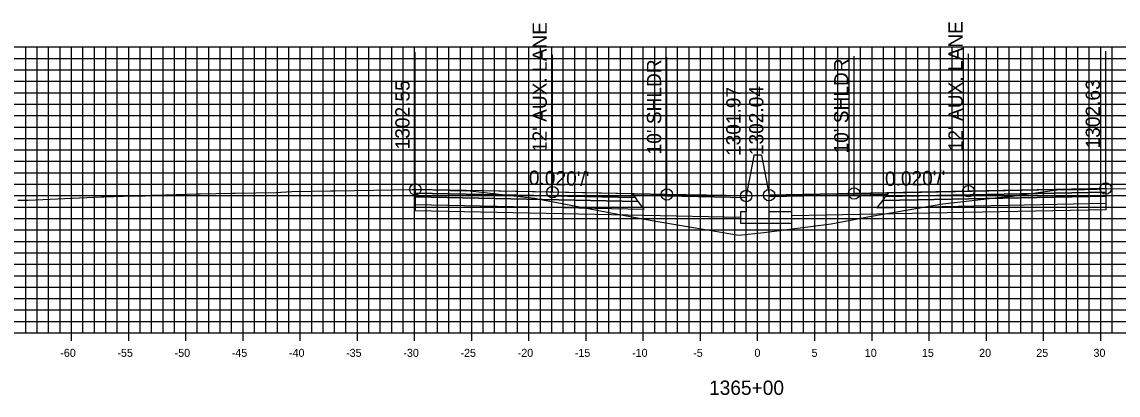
# Model space of a CAD drawing. Extents: x 674939 to 678919, y 750652 to 765176.
# Drawn here: x 678674.2 to 678770, y 754257.1 to 754289.7 of the extents above; entities that cross this region are included whole.
import ezdxf

# ---------------------------------------------------------------- set-up
doc = ezdxf.new("R2010")
doc.units = 0
for name, color, linetype in [('Level 10', 7, 'Continuous'), ('Level 17', 7, 'Continuous'), ('Level 18', 7, 'Continuous'), ('Level 19', 7, 'Continuous'), ('Level 20', 7, 'Continuous'), ('Level 22', 7, 'Continuous'), ('Level 23', 7, 'Continuous'), ('Level 4', 7, 'Continuous'), ('Level 8', 7, 'Continuous'), ('Level 9', 7, 'Continuous')]:
    doc.layers.add(name, color=color, linetype=linetype)

msp = doc.modelspace()

# ---------------------------------------------------------------- linework, layer by layer
at = {"layer": 'Level 10'}
msp.add_lwpolyline([(678673.826, 754274.146), (678674.4, 754274.144), (678674.446, 754274.145), (678674.752, 754274.161), (678681.152, 754274.436), (678681.365, 754274.444), (678683.059, 754274.507), (678684.564, 754274.521), (678684.623, 754274.523), (678684.656, 754274.525), (678684.987, 754274.544), (678685.002, 754274.546), (678685.611, 754274.58), (678685.824, 754274.586), (678689.588, 754274.707), (678689.789, 754274.712), (678692.612, 754274.752), (678692.848, 754274.757), (678696.424, 754274.838), (678696.448, 754274.837), (678696.823, 754274.85), (678696.859, 754274.855), (678697.8, 754274.9), (678701.187, 754274.964), (678701.519, 754274.97), (678701.59, 754274.972), (678708.326, 754275.093), (678708.596, 754275.097), (678708.599, 754275.097), (678708.635, 754275.098), (678710.141, 754275.048), (678710.236, 754275.044), (678710.247, 754275.046), (678711, 754275.056), (678711.565, 754275.019), (678711.707, 754275.012), (678713.024, 754274.978), (678713.042, 754274.98), (678713.133, 754274.991), (678716.186, 754274.644), (678718.748, 754274.354), (678719.049, 754274.317), (678719.41, 754274.249), (678720.813, 754273.978), (678727.53, 754272.685), (678729.62, 754272.316), (678736.874, 754271.1), (678739.064, 754271.34), (678744.951, 754272.082), (678748.499, 754272.75), (678754.715, 754273.846), (678760.098, 754274.436), (678760.79, 754274.511), (678761.024, 754274.543), (678764.912, 754275.094), (678764.938, 754275.087), (678765.147, 754275.054), (678765.749, 754275.074), (678767.146, 754275.101), (678767.508, 754275.105), (678768.207, 754275.117), (678768.737, 754275.163), (678768.966, 754275.178), (678768.994, 754275.181), (678769.067, 754275.185), (678772.003, 754275.143)], dxfattribs=at)
at = {"layer": 'Level 17'}
for points in [[(678738.203, 754278.019), (678737.533, 754274.519)], [(678738.863, 754278.09), (678738.863, 754278.09), (678738.203, 754278.09), (678738.203, 754278.019)], [(678738.863, 754278.09), (678739.533, 754274.59)], [(678737.533, 754274.519), (678737.533, 754273.144), (678737.033, 754273.144), (678737.033, 754272.144), (678741.533, 754272.144), (678741.533, 754273.144), (678739.533, 754273.144), (678739.533, 754274.59)]]:
    msp.add_lwpolyline(points, dxfattribs=at)
at = {"layer": 'Level 18'}
for points in [[(678737.533, 754274.519), (678730.596, 754274.657), (678720.596, 754274.857), (678708.596, 754275.097)], [(678768.966, 754275.178), (678756.966, 754274.938), (678746.966, 754274.738), (678739.533, 754274.59)]]:
    msp.add_lwpolyline(points, dxfattribs=at)
for points in [[(678708.596, 754275.097), (678708.596, 754274.767), (678727.846, 754274.382), (678727.596, 754274.717)], [(678768.966, 754275.178), (678768.966, 754274.848), (678749.716, 754274.463), (678749.966, 754274.798)], [(678727.596, 754274.717), (678737.533, 754274.519), (678737.537, 754274.361), (678727.715, 754274.557)], [(678749.847, 754274.639), (678739.533, 754274.433), (678739.533, 754274.59), (678749.966, 754274.798)]]:
    msp.add_lwpolyline(points, close=True, dxfattribs=at)
at = {"layer": 'Level 19'}
for points in [[(678708.596, 754274.767), (678708.596, 754274.437), (678728.096, 754274.047), (678727.846, 754274.382)], [(678708.596, 754274.437), (678708.596, 754273.777), (678728.596, 754273.377), (678728.096, 754274.047)], [(678768.966, 754274.518), (678768.966, 754273.858), (678748.966, 754273.458), (678749.466, 754274.128)], [(678768.966, 754274.848), (678768.966, 754274.518), (678749.466, 754274.128), (678749.716, 754274.463)]]:
    msp.add_lwpolyline(points, close=True, dxfattribs=at)
for points in [[(678708.596, 754273.777), (678708.596, 754273.237), (678728.596, 754272.837), (678737.033, 754272.669)], [(678768.966, 754273.858), (678768.966, 754273.318), (678748.966, 754272.918), (678741.533, 754272.77)]]:
    msp.add_lwpolyline(points, dxfattribs=at)
at = {"layer": 'Level 20'}
for p, q in [((678638.533, 754287.551), (678838.533, 754287.551)), ((678674.533, 754262.551), (678674.533, 754287.551)), ((678675.533, 754262.551), (678675.533, 754287.551)), ((678676.533, 754262.551), (678676.533, 754287.551)), ((678677.533, 754262.551), (678677.533, 754287.551)), ((678678.533, 754262.551), (678678.533, 754287.551)), ((678679.533, 754262.551), (678679.533, 754287.551)), ((678680.533, 754262.551), (678680.533, 754287.551)), ((678681.533, 754262.551), (678681.533, 754287.551)), ((678682.533, 754262.551), (678682.533, 754287.551)), ((678683.533, 754262.551), (678683.533, 754287.551)), ((678684.533, 754262.551), (678684.533, 754287.551)), ((678685.533, 754262.551), (678685.533, 754287.551)), ((678686.533, 754262.551), (678686.533, 754287.551)), ((678687.533, 754262.551), (678687.533, 754287.551)), ((678688.533, 754262.551), (678688.533, 754287.551)), ((678689.533, 754262.551), (678689.533, 754287.551)), ((678690.533, 754262.551), (678690.533, 754287.551)), ((678691.533, 754262.551), (678691.533, 754287.551)), ((678692.533, 754262.551), (678692.533, 754287.551)), ((678693.533, 754262.551), (678693.533, 754287.551)), ((678694.533, 754262.551), (678694.533, 754287.551)), ((678695.533, 754262.551), (678695.533, 754287.551)), ((678696.533, 754262.551), (678696.533, 754287.551)), ((678697.533, 754262.551), (678697.533, 754287.551)), ((678698.533, 754262.551), (678698.533, 754287.551)), ((678699.533, 754262.551), (678699.533, 754287.551)), ((678700.533, 754262.551), (678700.533, 754287.551)), ((678701.533, 754262.551), (678701.533, 754287.551)), ((678702.533, 754262.551), (678702.533, 754287.551)), ((678703.533, 754262.551), (678703.533, 754287.551)), ((678704.533, 754262.551), (678704.533, 754287.551)), ((678705.533, 754262.551), (678705.533, 754287.551)), ((678706.533, 754262.551), (678706.533, 754287.551)), ((678707.533, 754262.551), (678707.533, 754287.551)), ((678708.533, 754262.551), (678708.533, 754287.551)), ((678709.533, 754262.551), (678709.533, 754287.551)), ((678710.533, 754262.551), (678710.533, 754287.551)), ((678711.533, 754262.551), (678711.533, 754287.551)), ((678712.533, 754262.551), (678712.533, 754287.551)), ((678713.533, 754262.551), (678713.533, 754287.551)), ((678714.533, 754262.551), (678714.533, 754287.551)), ((678715.533, 754262.551), (678715.533, 754287.551)), ((678716.533, 754262.551), (678716.533, 754287.551)), ((678717.533, 754262.551), (678717.533, 754287.551)), ((678718.533, 754262.551), (678718.533, 754287.551)), ((678719.533, 754262.551), (678719.533, 754287.551)), ((678720.533, 754262.551), (678720.533, 754287.551)), ((678721.533, 754262.551), (678721.533, 754287.551)), ((678722.533, 754262.551), (678722.533, 754287.551)), ((678723.533, 754262.551), (678723.533, 754287.551)), ((678724.533, 754262.551), (678724.533, 754287.551)), ((678725.533, 754262.551), (678725.533, 754287.551)), ((678726.533, 754262.551), (678726.533, 754287.551)), ((678727.533, 754262.551), (678727.533, 754287.551)), ((678728.533, 754262.551), (678728.533, 754287.551)), ((678729.533, 754262.551), (678729.533, 754287.551)), ((678730.533, 754262.551), (678730.533, 754287.551)), ((678731.533, 754262.551), (678731.533, 754287.551)), ((678732.533, 754262.551), (678732.533, 754287.551)), ((678733.533, 754262.551), (678733.533, 754287.551)), ((678734.533, 754262.551), (678734.533, 754287.551)), ((678735.533, 754262.551), (678735.533, 754287.551)), ((678736.533, 754262.551), (678736.533, 754287.551)), ((678737.533, 754262.551), (678737.533, 754287.551)), ((678738.533, 754262.551), (678738.533, 754287.551)), ((678739.533, 754262.551), (678739.533, 754287.551)), ((678740.533, 754262.551), (678740.533, 754287.551)), ((678741.533, 754262.551), (678741.533, 754287.551)), ((678742.533, 754262.551), (678742.533, 754287.551)), ((678743.533, 754262.551), (678743.533, 754287.551)), ((678744.533, 754262.551), (678744.533, 754287.551)), ((678745.533, 754262.551), (678745.533, 754287.551)), ((678746.533, 754262.551), (678746.533, 754287.551)), ((678747.533, 754262.551), (678747.533, 754287.551)), ((678748.533, 754262.551), (678748.533, 754287.551)), ((678749.533, 754262.551), (678749.533, 754287.551)), ((678750.533, 754262.551), (678750.533, 754287.551)), ((678751.533, 754262.551), (678751.533, 754287.551)), ((678752.533, 754262.551), (678752.533, 754287.551)), ((678753.533, 754262.551), (678753.533, 754287.551)), ((678754.533, 754262.551), (678754.533, 754287.551)), ((678755.533, 754262.551), (678755.533, 754287.551)), ((678756.533, 754262.551), (678756.533, 754287.551)), ((678757.533, 754262.551), (678757.533, 754287.551)), ((678758.533, 754262.551), (678758.533, 754287.551)), ((678759.533, 754262.551), (678759.533, 754287.551)), ((678760.533, 754262.551), (678760.533, 754287.551)), ((678761.533, 754262.551), (678761.533, 754287.551)), ((678762.533, 754262.551), (678762.533, 754287.551)), ((678763.533, 754262.551), (678763.533, 754287.551)), ((678764.533, 754262.551), (678764.533, 754287.551)), ((678765.533, 754262.551), (678765.533, 754287.551)), ((678766.533, 754262.551), (678766.533, 754287.551)), ((678767.533, 754262.551), (678767.533, 754287.551)), ((678768.533, 754262.551), (678768.533, 754287.551)), ((678769.533, 754262.551), (678769.533, 754287.551)), ((678638.533, 754286.551), (678838.533, 754286.551)), ((678638.533, 754285.551), (678838.533, 754285.551)), ((678638.533, 754284.551), (678838.533, 754284.551)), ((678638.533, 754283.551), (678838.533, 754283.551)), ((678638.533, 754282.551), (678838.533, 754282.551)), ((678638.533, 754281.551), (678838.533, 754281.551)), ((678638.533, 754280.551), (678838.533, 754280.551)), ((678638.533, 754279.551), (678838.533, 754279.551)), ((678638.533, 754278.551), (678838.533, 754278.551)), ((678638.533, 754277.551), (678838.533, 754277.551)), ((678638.533, 754276.551), (678838.533, 754276.551)), ((678638.533, 754275.551), (678838.533, 754275.551)), ((678638.533, 754274.551), (678838.533, 754274.551)), ((678638.533, 754273.551), (678838.533, 754273.551)), ((678638.533, 754272.551), (678838.533, 754272.551)), ((678638.533, 754271.551), (678838.533, 754271.551)), ((678638.533, 754270.551), (678838.533, 754270.551)), ((678638.533, 754269.551), (678838.533, 754269.551)), ((678638.533, 754268.551), (678838.533, 754268.551)), ((678638.533, 754267.551), (678838.533, 754267.551)), ((678638.533, 754266.551), (678838.533, 754266.551)), ((678638.533, 754265.551), (678838.533, 754265.551)), ((678638.533, 754264.551), (678838.533, 754264.551)), ((678638.533, 754263.551), (678838.533, 754263.551)), ((678638.533, 754262.551), (678838.533, 754262.551))]:
    msp.add_line(p, q, dxfattribs=at)
at = {"layer": 'Level 23'}
for p, q in [((678708.596, 754275.097), (678708.596, 754287.097)), ((678720.596, 754274.857), (678720.596, 754286.857)), ((678730.596, 754274.657), (678730.596, 754286.657)), ((678739.533, 754274.59), (678739.533, 754286.59)), ((678746.966, 754274.738), (678746.966, 754286.738)), ((678756.966, 754274.938), (678756.966, 754286.938)), ((678768.966, 754275.178), (678768.966, 754287.178)), ((678737.533, 754274.519), (678737.533, 754286.519))]:
    msp.add_line(p, q, dxfattribs=at)
at = {"layer": 'Level 4'}
for centre in [(678708.596, 754275.097), (678720.596, 754274.857), (678730.596, 754274.657), (678739.533, 754274.59), (678746.966, 754274.738), (678756.966, 754274.938), (678768.966, 754275.178), (678737.533, 754274.519)]:
    msp.add_circle(centre, 0.5, dxfattribs=at)
at = {"layer": 'Level 8'}
for p, q in [((678678.533, 754261.851), (678678.533, 754263.251)), ((678683.533, 754261.851), (678683.533, 754263.251)), ((678688.533, 754261.851), (678688.533, 754263.251)), ((678693.533, 754261.851), (678693.533, 754263.251)), ((678698.533, 754261.851), (678698.533, 754263.251)), ((678703.533, 754261.851), (678703.533, 754263.251)), ((678708.533, 754261.851), (678708.533, 754263.251)), ((678713.533, 754261.851), (678713.533, 754263.251)), ((678718.533, 754261.851), (678718.533, 754263.251)), ((678723.533, 754261.851), (678723.533, 754263.251)), ((678728.533, 754261.851), (678728.533, 754263.251)), ((678733.533, 754261.851), (678733.533, 754263.251)), ((678738.533, 754261.851), (678738.533, 754263.251)), ((678743.533, 754261.851), (678743.533, 754263.251)), ((678748.533, 754261.851), (678748.533, 754263.251)), ((678753.533, 754261.851), (678753.533, 754263.251)), ((678758.533, 754261.851), (678758.533, 754263.251)), ((678763.533, 754261.851), (678763.533, 754263.251)), ((678768.533, 754261.851), (678768.533, 754263.251)), ((678638.533, 754262.551), (678838.533, 754262.551))]:
    msp.add_line(p, q, dxfattribs=at)

# ---------------------------------------------------------------- texts
at = {"layer": 'Level 22'}
for rotation, p in [(358.85424, (678718.515, 754275.499)), (1.14576, (678749.676, 754275.393))]:
    msp.add_text("0.020'/'", height=1.25, rotation=rotation, dxfattribs=at).set_placement(p)
at = {"layer": 'Level 23'}
for s, p in [("12' AUX. LANE", (678720.096, 754278.357)), ("12' AUX. LANE", (678756.466, 754278.438)), ("10' SHLDR", (678730.096, 754278.157)), ("10' SHLDR", (678746.466, 754278.238)), ('1302.63', (678768.466, 754278.678)), ('1302.55', (678708.096, 754278.597)), ('1301.97', (678737.033, 754278.019)), ('1302.04', (678739.033, 754278.09))]:
    msp.add_text(s, height=1.25, rotation=90, dxfattribs=at).set_placement(p)
at = {"layer": 'Level 9'}
for s, height, p in [('-60', 0.7, (678677.552, 754260.451)), ('-55', 0.7, (678682.546, 754260.451)), ('-50', 0.7, (678687.552, 754260.451)), ('-45', 0.7, (678692.546, 754260.451)), ('-40', 0.7, (678697.552, 754260.451)), ('-35', 0.7, (678702.546, 754260.451)), ('-30', 0.7, (678707.552, 754260.451)), ('-25', 0.7, (678712.546, 754260.451)), ('-20', 0.7, (678717.552, 754260.451)), ('-15', 0.7, (678722.546, 754260.451)), ('-10', 0.7, (678727.552, 754260.451)), ('-5', 0.7, (678732.896, 754260.451)), ('0', 0.7, (678738.252, 754260.451)), ('5', 0.7, (678743.246, 754260.451)), ('10', 0.7, (678747.902, 754260.451)), ('15', 0.7, (678752.896, 754260.451)), ('20', 0.7, (678757.902, 754260.451)), ('25', 0.7, (678762.896, 754260.451)), ('30', 0.7, (678767.902, 754260.451)), ('1365+00', 1.25, (678734.282, 754257.126))]:
    msp.add_text(s, height=height, dxfattribs=at).set_placement(p)

doc.saveas('drawing.dxf')
